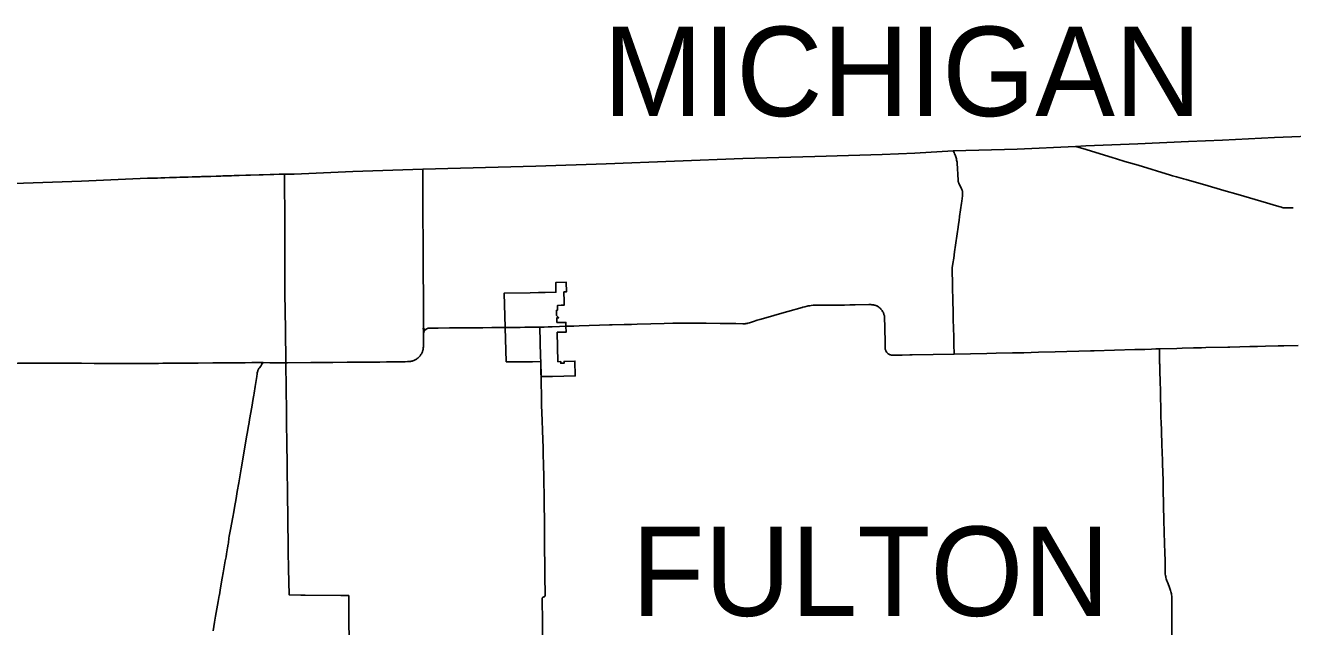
# Model space of a CAD drawing. Extents: x -786946 to -767280, y 417139 to 426807.
# Drawn here: x -783620 to -780299, y 425231 to 426807 of the extents above; entities that cross this region are included whole.
import ezdxf

# ---------------------------------------------------------------- set-up
doc = ezdxf.new("R2010")
doc.units = 0
for name, color, linetype in [('DV_X_Corp_Line', 7, 'Continuous'), ('DV_X_County_Line', 7, 'Continuous'), ('GM_X_State_Route', 7, 'Continuous'), ('SH_Text', 7, 'Continuous')]:
    doc.layers.add(name, color=color, linetype=linetype)

msp = doc.modelspace()

# ---------------------------------------------------------------- linework, layer by layer
at = {"layer": 'DV_X_Corp_Line'}
msp.add_lwpolyline([(-782224.8, 425925.3), (-782217.2, 425925.6), (-782216.9, 425921.4), (-782208, 425921.7), (-782208.2, 425925.9), (-782179.8, 425926.9), (-782178.9, 425888), (-782238.8, 425886.8), (-782268.7, 425886.7), (-782269.6, 425925.5), (-782291.3, 425925.3), (-782304.5, 425925.3), (-782359.9, 425925.1), (-782365.5, 426104.8), (-782297.1, 426106), (-782275.2, 426106.4), (-782257.9, 426106.9), (-782229.5, 426107.5), (-782229.9, 426133.3), (-782202.9, 426134.1), (-782202.1, 426108.3), (-782208.8, 426108.1), (-782207.9, 426082.9), (-782207.7, 426073.9), (-782215.5, 426073.1), (-782225.8, 426072.6), (-782225.6, 426065.9), (-782225.9, 426062.5), (-782225.8, 426060), (-782228, 426060), (-782227.9, 426046.1), (-782222.1, 426040.3), (-782227.4, 426040), (-782226.9, 426028.1), (-782203.5, 426028.3), (-782203.3, 426018), (-782202.9, 426002.7), (-782226, 426002.4)], close=True, dxfattribs=at)
at = {"layer": 'DV_X_County_Line'}
for points in [[(-782771.4, 425130.2), (-782772.4, 425312.1), (-782793.1, 425312.2), (-782887, 425313.2), (-782888.8, 425313.2), (-782892.5, 425313.3), (-782898.3, 425313.5), (-782928.9, 425314.4), (-782930.5, 425382), (-782930.6, 425384.6), (-782930.6, 425387.8), (-782930.7, 425393), (-782930.7, 425400.1), (-782930.9, 425410.7), (-782931, 425422.2), (-782931.1, 425431.4), (-782931.2, 425434.9), (-782931.4, 425443.2), (-782931.4, 425448.7), (-782931.5, 425459.1), (-782931.7, 425471.2), (-782931.8, 425479.5), (-782932, 425493.2), (-782932.1, 425504), (-782932.2, 425511), (-782932.3, 425519), (-782932.4, 425523.2), (-782932.4, 425525.2), (-782932.4, 425527.1), (-782932.6, 425539.8), (-782932.7, 425554.3), (-782932.8, 425561.6), (-782932.8, 425565.5), (-782932.9, 425571.9), (-782933, 425576.8), (-782933, 425580), (-782933.1, 425584.5), (-782933.1, 425589.9), (-782933.2, 425595.2), (-782933.3, 425602.7), (-782933.3, 425608.1), (-782933.5, 425616.1), (-782933.6, 425625.2), (-782933.7, 425632.6), (-782933.7, 425640.1), (-782933.9, 425648.6), (-782934.1, 425665.7), (-782934.2, 425670.7), (-782934.3, 425680.6), (-782934.4, 425687.8), (-782934.6, 425696.7), (-782934.7, 425707.2), (-782935.1, 425726.1), (-782935.2, 425735.4), (-782935.3, 425740.7), (-782935.4, 425741.5), (-782935.4, 425743), (-782935.5, 425752.1), (-782935.6, 425772.3), (-782935.7, 425782.3), (-782935.7, 425787.4), (-782935.8, 425796.7), (-782935.8, 425802.7), (-782936, 425819.7), (-782936.1, 425830.8), (-782936.2, 425838.7), (-782936.3, 425845), (-782936.4, 425851), (-782936.5, 425860.3), (-782936.6, 425870.1), (-782936.8, 425882.8), (-782937, 425893.4), (-782937.1, 425903.6), (-782937.2, 425912.3), (-782937.4, 425922.6), (-782938.6, 426011), (-782939.8, 426104.1), (-782940.2, 426284), (-782941.2, 426417.1), (-782915.4, 426417.3), (-782761.6, 426424.2), (-782578.3, 426430.2), (-782282.2, 426437.5), (-782098, 426444.3), (-781919.2, 426450.6), (-781739.7, 426458.1), (-781551.5, 426463.2), (-781375.1, 426468.8), (-781289.6, 426471.9), (-781188.5, 426477.8), (-781021.2, 426482.7), (-780868.4, 426489.6), (-780840.8, 426490.9), (-780705.2, 426496.6), (-780572.2, 426502.4), (-780483.3, 426506.3), (-780346.7, 426513.1), (-780301.3, 426514.5), (-780212.1, 426518.6)], [(-783650, 426392.7), (-783473.2, 426398.2), (-783300.2, 426406.5), (-783298.5, 426406.3), (-783296.4, 426406.1), (-783293.6, 426406.1), (-783288.5, 426406.1), (-783281.4, 426406.4), (-783273.9, 426406.7), (-783264.9, 426407), (-783254.9, 426407.4), (-783242.3, 426407.8), (-783234.8, 426408), (-783223.9, 426408.4), (-783215.1, 426408.6), (-783208.1, 426408.8), (-783192.9, 426409.3), (-783182.6, 426409.7), (-783171.9, 426410), (-783162.3, 426410.2), (-783158.2, 426410.4), (-783146.1, 426410.7), (-783133.8, 426411.1), (-783119.7, 426411.6), (-783115.4, 426411.7), (-783107.5, 426412), (-783102.5, 426412.2), (-783092.6, 426412.5), (-783087, 426412.6), (-783079.8, 426412.9), (-783073.2, 426413.1), (-783060, 426413.6), (-783042.3, 426414.1), (-783030.9, 426414.5), (-783030.1, 426414.5), (-783007.5, 426415.1), (-782996.4, 426415.5), (-782978.6, 426416), (-782968.9, 426416.3), (-782955, 426416.7), (-782941.2, 426417.1), (-782940.2, 426284), (-782939.8, 426104.1), (-782938.6, 426011), (-782937.4, 425922.6), (-782937.2, 425912.3), (-782937.1, 425903.6), (-782937, 425893.4), (-782936.8, 425882.8), (-782936.6, 425870.1), (-782936.5, 425860.3), (-782936.4, 425851), (-782936.3, 425845), (-782936.2, 425838.7), (-782936.1, 425830.8), (-782936, 425819.7), (-782935.8, 425802.7), (-782935.8, 425796.7), (-782935.7, 425787.4), (-782935.7, 425782.3), (-782935.6, 425772.3), (-782935.5, 425752.1), (-782935.4, 425743), (-782935.4, 425741.5), (-782935.3, 425740.7), (-782935.2, 425735.4), (-782935.1, 425726.1), (-782934.7, 425707.2), (-782934.6, 425696.7), (-782934.4, 425687.8), (-782934.3, 425680.6), (-782934.2, 425670.7), (-782934.1, 425665.7), (-782933.9, 425648.6), (-782933.7, 425640.1), (-782933.7, 425632.6), (-782933.6, 425625.2), (-782933.5, 425616.1), (-782933.3, 425608.1), (-782933.3, 425602.7), (-782933.2, 425595.2), (-782933.1, 425589.9), (-782933.1, 425584.5), (-782933, 425580), (-782933, 425576.8), (-782932.9, 425571.9), (-782932.8, 425565.5), (-782932.8, 425561.6), (-782932.7, 425554.3), (-782932.6, 425539.8), (-782932.4, 425527.1), (-782932.4, 425525.2), (-782932.4, 425523.2), (-782932.3, 425519), (-782932.2, 425511), (-782932.1, 425504), (-782932, 425493.2), (-782931.8, 425479.5), (-782931.7, 425471.2), (-782931.5, 425459.1), (-782931.4, 425448.7), (-782931.4, 425443.2), (-782931.2, 425434.9), (-782931.1, 425431.4), (-782931, 425422.2), (-782930.9, 425410.7), (-782930.7, 425400.1), (-782930.7, 425393), (-782930.6, 425387.8), (-782930.6, 425384.6), (-782930.5, 425382), (-782928.9, 425314.4), (-782898.3, 425313.5), (-782892.5, 425313.3), (-782888.8, 425313.2), (-782887, 425313.2), (-782793.1, 425312.2), (-782772.4, 425312.1), (-782771.4, 425130.2)]]:
    msp.add_lwpolyline(points, dxfattribs=at)
at = {"layer": 'GM_X_State_Route'}
for p, q in [((-781187.4, 425990.5), (-781188.4, 426035.5)), ((-782272, 426015.9), (-782261.7, 426016.1)), ((-782271.8, 426009.5), (-782272, 426015.9)), ((-780712.9, 425956.9), (-780686.2, 425957.7)), ((-780686.2, 425957.7), (-780712.9, 425956.9)), ((-783317.9, 425920.9), (-783308.8, 425920.9)), ((-782260.5, 425565.4), (-782260.7, 425575.3)), ((-783111.6, 425313.2), (-783111.5, 425313.9))]:
    msp.add_line(p, q, dxfattribs=at)
for points in [[(-781177.5, 426431.8), (-781178.4, 426444.6), (-781178.7, 426447.9), (-781179.2, 426451.2), (-781179.7, 426454), (-781180.3, 426456.7), (-781180.9, 426459.4), (-781181.7, 426462.1), (-781182.8, 426465.3), (-781183.8, 426467.9), (-781184.9, 426470.5), (-781186.3, 426473.5), (-781188.5, 426477.9)], [(-780868.4, 426489.7), (-780854.9, 426485.5), (-780840.6, 426481.2), (-780781.2, 426463.1), (-780772.2, 426460.5), (-780760.4, 426456.9), (-780738.5, 426450.4), (-780704.3, 426440.1), (-780618.9, 426414.3), (-780613.6, 426412.8), (-780603.9, 426410.1), (-780585.6, 426405), (-780578.2, 426402.8), (-780569.8, 426400.4), (-780529.4, 426388.6), (-780479.9, 426374.2), (-780442.1, 426363.3), (-780367.3, 426341.3), (-780359.2, 426339), (-780341.5, 426333.8), (-780332, 426330.9), (-780328.8, 426330), (-780326.6, 426329.5), (-780323.9, 426329), (-780321.7, 426328.7), (-780319.4, 426328.5), (-780316.7, 426328.3), (-780312.8, 426328.3), (-780297.7, 426328.6)], [(-782576.9, 426014.3), (-782576.9, 426016.8), (-782577, 426017.4), (-782576.9, 426033), (-782576.9, 426052), (-782576.9, 426070.5), (-782577, 426087.3), (-782577, 426103.3), (-782577, 426106.7), (-782577.2, 426149.9), (-782577.3, 426175.6), (-782577.4, 426190.2), (-782577.7, 426229.9), (-782577.8, 426256.7), (-782577.9, 426265.7), (-782578, 426281.8), (-782578, 426286.6), (-782578.1, 426303.7), (-782578.2, 426323.8), (-782578.3, 426352.3), (-782578.5, 426374.8), (-782578.4, 426411.6), (-782578.3, 426430.3)], [(-781188.4, 426035.5), (-781188.7, 426050.9), (-781189.7, 426090), (-781190.3, 426116.3), (-781190.5, 426125), (-781190.6, 426129.7), (-781191.5, 426165.5), (-781191.5, 426167.7), (-781191.4, 426169.4), (-781191.1, 426171.6), (-781189.4, 426182.6), (-781187.4, 426197), (-781185, 426213.6), (-781182.6, 426230.8), (-781178.4, 426260.1), (-781175.8, 426277.8), (-781174.6, 426286.1), (-781173.4, 426295.6), (-781171.9, 426306), (-781166.7, 426340.9), (-781166, 426346.5), (-781164.6, 426359.8), (-781164.2, 426363.7), (-781164.1, 426365.9), (-781164.2, 426368.2), (-781164.3, 426370.4), (-781164.5, 426372), (-781164.9, 426373.7), (-781165.3, 426375.3), (-781165.9, 426376.8), (-781166.6, 426378.4), (-781168.8, 426382.9), (-781172.8, 426390.9), (-781173.7, 426392.9), (-781174.4, 426394.5), (-781174.9, 426396.1), (-781175.3, 426397.7), (-781175.6, 426399.4), (-781175.7, 426401.1), (-781176.4, 426416.1), (-781177.5, 426431.8)], [(-781758.6, 426025), (-781740.3, 426024.7), (-781736.4, 426024.7), (-781734.1, 426024.8), (-781731.9, 426025.1), (-781731.4, 426025.2), (-781730.3, 426025.3), (-781728.6, 426025.7), (-781726.5, 426026.3), (-781722.2, 426027.6), (-781711.6, 426031), (-781702.5, 426033.8), (-781695.1, 426036), (-781673.6, 426042.1), (-781643.6, 426050.6), (-781621.6, 426056.9), (-781584.2, 426067.5)], [(-781584.2, 426067.5), (-781582.5, 426068), (-781577.1, 426069.4), (-781571.7, 426070.7), (-781568.4, 426071.4), (-781564.6, 426072.1), (-781560.7, 426072.6), (-781555.2, 426073.2), (-781551.9, 426073.5), (-781548, 426073.6), (-781544.8, 426073.7), (-781538, 426073.7), (-781534.6, 426073.6)], [(-781534.6, 426073.6), (-781508.4, 426073.4), (-781499.5, 426073.4), (-781491.7, 426073.5), (-781473.9, 426073.9), (-781459.4, 426074.3), (-781454.3, 426074.4), (-781445.5, 426074.5), (-781409.3, 426074.8), (-781404.3, 426074.8), (-781401.5, 426074.7), (-781400.3, 426074.6), (-781399.3, 426074.5), (-781397.6, 426074.2), (-781396, 426073.9), (-781393.9, 426073.3), (-781391.8, 426072.6), (-781390.9, 426072.3)], [(-781390.9, 426072.3), (-781390.2, 426072), (-781388.7, 426071.3), (-781387.2, 426070.6), (-781385.8, 426069.7), (-781384.4, 426068.8), (-781382.6, 426067.5), (-781380.9, 426066.1), (-781379.2, 426064.6), (-781378.1, 426063.4), (-781377, 426062.2), (-781375.6, 426060.4), (-781374.6, 426059.1), (-781373.5, 426057.2), (-781372.4, 426055.2), (-781371.7, 426053.7), (-781371, 426052.2), (-781370.5, 426050.6), (-781370, 426049), (-781369.6, 426047.4), (-781369.1, 426045.2), (-781368.8, 426043), (-781368.6, 426040.4)], [(-781368.6, 426040.4), (-781368.6, 426040.4), (-781368.5, 426038), (-781368.4, 426033.2), (-781368.2, 426024), (-781367, 425965.1), (-781366.8, 425961.2), (-781366.7, 425959.2)], [(-782578.3, 425955.5), (-782577.9, 425957.1), (-782577.6, 425959.3), (-782577.3, 425961.5), (-782577.1, 425964.3), (-782577, 425967.7), (-782577, 425977.2), (-782576.9, 425984.4), (-782576.5, 425998), (-782576, 426001.4), (-782575.8, 426002.5), (-782575.5, 426003.6), (-782575.1, 426004.7), (-782574.6, 426005.7), (-782574, 426006.7), (-782573, 426008.2), (-782572.5, 426008.7)], [(-782578.3, 425955.5), (-782577.9, 425957.1), (-782577.6, 425959.3), (-782577.3, 425961.5), (-782577.1, 425964.3), (-782577, 425967.7), (-782577, 425977.2), (-782576.9, 425984.4), (-782576.5, 425998), (-782576, 426001.4), (-782575.8, 426002.5), (-782575.5, 426003.6), (-782575.1, 426004.7), (-782574.6, 426005.7), (-782574, 426006.7), (-782573, 426008.2), (-782572.5, 426008.7)], [(-782577.1, 426006.9), (-782577.2, 426013.3), (-782576.9, 426014.3)], [(-782576.5, 425998), (-782576.8, 425999.6), (-782576.9, 426000.8), (-782577, 426002.1), (-782577.1, 426005.1), (-782577.1, 426006.9)], [(-782572.5, 426008.7), (-782574.8, 426010.7), (-782576, 426012), (-782576.5, 426012.8), (-782576.7, 426013.2), (-782576.8, 426013.7), (-782576.9, 426014.3)], [(-782572.5, 426008.7), (-782570.9, 426010), (-782570, 426010.7), (-782568.3, 426011.7), (-782567.4, 426012.1), (-782566.1, 426012.6), (-782565.3, 426012.8), (-782563.2, 426013.1), (-782560.2, 426013.2), (-782557.9, 426013.3)], [(-782557.9, 426013.3), (-782555.7, 426013.4), (-782537.9, 426013.6), (-782508.3, 426013.9), (-782420.8, 426014.4), (-782397.9, 426014.6), (-782391.8, 426014.6), (-782373.4, 426014.8), (-782365.6, 426014.9), (-782362.8, 426015)], [(-782362.8, 426015), (-782362.7, 426015), (-782336.1, 426015.2)], [(-782336.1, 426015.2), (-782334.8, 426015.2), (-782330, 426015.1), (-782323.8, 426015.3), (-782311, 426015.4), (-782305, 426015.5), (-782294.3, 426015.7)], [(-782294.3, 426015.7), (-782293.7, 426015.7), (-782283.3, 426015.8)], [(-782283.3, 426015.8), (-782283, 426015.8), (-782272, 426015.9)], [(-782271.4, 425998.5), (-782271.5, 425999.6), (-782271.6, 426004.6), (-782271.8, 426009.5)], [(-782269.6, 425925.5), (-782269.6, 425928.1), (-782269.8, 425935.4), (-782270, 425939.9), (-782270.2, 425948.8), (-782270.3, 425950.5), (-782270.4, 425953.3), (-782270.6, 425962.8), (-782270.6, 425964.5), (-782270.7, 425967.8), (-782270.8, 425972.3), (-782271, 425980.1), (-782271.2, 425988.4), (-782271.3, 425993.8), (-782271.4, 425998.5)], [(-782261.7, 426016.1), (-782260.8, 426016.1), (-782250.2, 426016.6), (-782244.3, 426016.8), (-782239.5, 426016.9), (-782220.5, 426017.5), (-782203.3, 426018), (-782203.3, 426018)], [(-782203.3, 426018), (-782198.1, 426018.2), (-782187.5, 426018.6), (-782182.8, 426018.7)], [(-782182.8, 426018.7), (-782168.6, 426019.2), (-782088.9, 426021.8), (-782082.4, 426021.9)], [(-782082.4, 426021.9), (-782050.5, 426022.7), (-782031.6, 426023.2), (-782016.5, 426023.5), (-781980.9, 426024.4), (-781946.4, 426025.5), (-781923, 426026.1), (-781910, 426026.3), (-781906.8, 426026.4), (-781885.7, 426026.2), (-781864.5, 426026), (-781855, 426026), (-781836.1, 426025.9), (-781799.3, 426025.5), (-781758.6, 426025)], [(-781186.4, 425945.2), (-781186.5, 425950.8), (-781186.7, 425964.8), (-781187, 425977.1), (-781187.3, 425986), (-781187.4, 425990.5)], [(-780648.4, 425958.8), (-780602.8, 425960.1), (-780588.3, 425960.6), (-780558.9, 425961.4), (-780541.5, 425961.9), (-780537.7, 425962)], [(-780537.7, 425962), (-780526.5, 425962.2), (-780469.2, 425963.6), (-780463.5, 425963.8), (-780411.7, 425965), (-780391.7, 425965.3), (-780370.5, 425965.7), (-780337.1, 425966.7), (-780330.9, 425966.9), (-780322.6, 425967.1), (-780284.8, 425967.6)], [(-782611.3, 425926), (-782610.9, 425926), (-782608.7, 425926.4), (-782606.6, 425926.9), (-782604.4, 425927.5), (-782602.3, 425928.2), (-782600.3, 425929.1), (-782598.7, 425929.8), (-782596.8, 425930.8), (-782594.9, 425932), (-782593.1, 425933.3), (-782591.3, 425934.6), (-782589.7, 425936.1), (-782588.1, 425937.7), (-782587, 425938.9), (-782585.5, 425940.6), (-782584.2, 425942.4), (-782583.3, 425943.8), (-782582.2, 425945.7), (-782581, 425947.9), (-782580.2, 425949.7), (-782579.6, 425951.2), (-782579, 425952.8), (-782578.4, 425954.9), (-782578.3, 425955.5)], [(-782611.3, 425926), (-782610.9, 425926), (-782608.7, 425926.4), (-782606.6, 425926.9), (-782604.4, 425927.5), (-782602.3, 425928.2), (-782600.3, 425929.1), (-782598.7, 425929.8), (-782596.8, 425930.8), (-782594.9, 425932), (-782593.1, 425933.3), (-782591.3, 425934.6), (-782589.7, 425936.1), (-782588.1, 425937.7), (-782587, 425938.9), (-782585.5, 425940.6), (-782584.2, 425942.4), (-782583.3, 425943.8), (-782582.2, 425945.7), (-782581, 425947.9), (-782580.2, 425949.7), (-782579.6, 425951.2), (-782579, 425952.8), (-782578.4, 425954.9), (-782578.3, 425955.5)], [(-781366.7, 425959.2), (-781366.5, 425958), (-781366.1, 425956.4), (-781365.6, 425954.8), (-781364.9, 425953.3)], [(-781364.9, 425953.3), (-781364.1, 425951.8), (-781363.1, 425950.4), (-781362.1, 425949.1), (-781361.3, 425948.2), (-781360.1, 425947.1), (-781358.7, 425946), (-781357.3, 425945.1), (-781355.9, 425944.3), (-781354.3, 425943.6), (-781352.9, 425943.1), (-781350.5, 425942.4), (-781349.4, 425942.3), (-781346.1, 425942.2), (-781337.2, 425942.4), (-781322.1, 425942.7), (-781302.6, 425943.1), (-781295.9, 425943.2), (-781186.4, 425945.2)], [(-781186.4, 425945.2), (-781100.5, 425946.9), (-781076.5, 425947.4), (-781033.1, 425948.3), (-781003.6, 425948.9), (-780965.1, 425949.9), (-780921.7, 425951), (-780828.6, 425953.4), (-780819.3, 425953.6), (-780712.9, 425956.9)], [(-780712.9, 425956.9), (-780819.3, 425953.6), (-780828.6, 425953.4), (-780921.7, 425951), (-780965.1, 425949.9), (-781003.6, 425948.9), (-781033.1, 425948.3), (-781076.5, 425947.4), (-781100.5, 425946.9), (-781186.4, 425945.2)], [(-780686.2, 425957.7), (-780669.2, 425958.3), (-780657.5, 425958.6), (-780648.4, 425958.8)], [(-780648.4, 425958.8), (-780657.5, 425958.6), (-780669.2, 425958.3), (-780686.2, 425957.7)], [(-780638.7, 425597.3), (-780638.9, 425618.7), (-780639.1, 425630.4), (-780640, 425662.8), (-780640.4, 425671.8), (-780640.7, 425682.4), (-780641.8, 425713.1), (-780642.1, 425720.4), (-780642.5, 425730.4), (-780643, 425744.4), (-780643.9, 425767.8), (-780644.2, 425778.1), (-780645, 425808.6), (-780645.4, 425828.2), (-780645.8, 425841), (-780646.7, 425881.3), (-780647, 425892.4), (-780647.6, 425918.1), (-780647.7, 425920.4), (-780647.7, 425924.3), (-780647.7, 425926.8), (-780648, 425940.4), (-780648.3, 425951.5), (-780648.4, 425958.8)], [(-783650.5, 425920.3), (-783643.5, 425920.9), (-783639.5, 425921.2), (-783635.1, 425921.3), (-783579.5, 425921.3), (-783565.8, 425921.2), (-783532.4, 425921.2), (-783524.3, 425921.2), (-783495.7, 425921.2), (-783473.2, 425921.1), (-783439.9, 425921), (-783414.6, 425920.9), (-783397.2, 425920.9), (-783379.7, 425920.8), (-783355.1, 425920.9), (-783332.6, 425920.9), (-783321.7, 425921)], [(-783321.7, 425921), (-783321.5, 425921), (-783317.9, 425920.9)], [(-783308.8, 425920.9), (-783305.7, 425920.9), (-783294.1, 425920.9), (-783282.6, 425920.9), (-783270.9, 425921), (-783260.1, 425921.1)], [(-783260.1, 425921.1), (-783248.6, 425921.1), (-783236.6, 425921.2), (-783225.3, 425921.3), (-783213.8, 425921.3), (-783205.2, 425921.4), (-783202.5, 425921.4)], [(-783202.5, 425921.4), (-783196.9, 425921.5), (-783177.4, 425921.6), (-783166.7, 425921.6)], [(-783166.7, 425921.6), (-783128.7, 425921.9), (-783104.5, 425922.1), (-783043.9, 425922.7), (-783026.4, 425922.8), (-783012.6, 425922.8), (-783002.1, 425922.8), (-782997, 425922.8)], [(-783111.5, 425313.9), (-783108.2, 425332.8), (-783103.8, 425357.7), (-783101.4, 425371.7), (-783096, 425402.9), (-783094.1, 425413.4), (-783092.7, 425421.8), (-783089.9, 425437), (-783088.2, 425447.4), (-783087.7, 425450.8), (-783087.5, 425452.9), (-783086.8, 425460.2), (-783086.5, 425462.9), (-783085.6, 425468), (-783084, 425477.1), (-783082.5, 425485), (-783076.5, 425517.7), (-783074, 425532), (-783071.1, 425548.7), (-783068.8, 425561.3), (-783066.8, 425573), (-783064.5, 425585.4), (-783060.6, 425608), (-783054.1, 425644.6), (-783050.8, 425664.4), (-783044.6, 425702.3), (-783041.2, 425722.5), (-783040.3, 425728.2), (-783038, 425741.7), (-783036.1, 425752.7), (-783034.6, 425761.3), (-783033.8, 425766.1), (-783032.5, 425773.6), (-783026.9, 425806.1), (-783022.9, 425829.1), (-783021.4, 425837.7), (-783020.6, 425843.2), (-783017.7, 425860.1), (-783013.7, 425886.2), (-783012.6, 425893.2), (-783012.1, 425896.1), (-783011.6, 425898.4), (-783011.1, 425900.2), (-783010.5, 425902), (-783009.7, 425903.8), (-783008.8, 425905.6), (-783007.8, 425907.3), (-783006.6, 425909.2), (-783003.2, 425913.7), (-783000, 425918.5), (-782997, 425922.8)], [(-783000, 425918.5), (-783000, 425919.1), (-783000.2, 425920), (-783000.4, 425920.7), (-783000.7, 425921.2), (-783001.1, 425921.7), (-783001.6, 425922.3), (-783002.1, 425922.8)], [(-782997, 425922.8), (-782979.7, 425922.7), (-782937.5, 425922.7)], [(-782997, 425922.8), (-782979.7, 425922.7), (-782937.5, 425922.7)], [(-782937.5, 425922.7), (-782932.8, 425922.7), (-782871.5, 425923.3), (-782855.9, 425923.4), (-782849.8, 425923.5), (-782838.6, 425923.5), (-782822.5, 425923.6), (-782814.1, 425923.5), (-782776.8, 425923.7), (-782759, 425923.8), (-782754, 425923.8), (-782745.1, 425923.9), (-782737.8, 425923.9), (-782728.9, 425924.1), (-782691, 425924.5), (-782673.2, 425924.7), (-782644.8, 425925.1), (-782624.8, 425925.3), (-782618.7, 425925.4), (-782615.3, 425925.6), (-782613.1, 425925.8), (-782611.3, 425926)], [(-782937.5, 425922.7), (-782932.8, 425922.7), (-782871.5, 425923.3), (-782855.9, 425923.4), (-782849.8, 425923.5), (-782838.6, 425923.5), (-782822.5, 425923.6), (-782814.1, 425923.5), (-782776.8, 425923.7), (-782759, 425923.8), (-782754, 425923.8), (-782745.1, 425923.9), (-782737.8, 425923.9), (-782728.9, 425924.1), (-782691, 425924.5), (-782673.2, 425924.7), (-782644.8, 425925.1), (-782624.8, 425925.3), (-782618.7, 425925.4), (-782615.3, 425925.6), (-782613.1, 425925.8), (-782611.3, 425926)], [(-782268.7, 425886.7), (-782268.9, 425893.7), (-782269.2, 425908.2), (-782269.6, 425925.5)], [(-782261.5, 425615), (-782261.6, 425622.2), (-782262.2, 425656.8), (-782262.8, 425680.9), (-782263, 425686.5), (-782263.5, 425698.2), (-782265.1, 425745), (-782266, 425771.3), (-782266.6, 425790.9), (-782267.1, 425811.6), (-782267.2, 425818.8), (-782267.6, 425841.7), (-782268.1, 425864.7), (-782268.5, 425877.3), (-782268.7, 425886.7)], [(-782260.7, 425575.3), (-782261.4, 425610.5), (-782261.5, 425615)], [(-780633.2, 425376.2), (-780633.4, 425381.9), (-780633.6, 425396.4), (-780634.5, 425432.1), (-780634.6, 425440.5), (-780635.8, 425486.1), (-780636.3, 425501.9), (-780636.5, 425512), (-780637.4, 425545.5), (-780637.6, 425555), (-780638.4, 425586.3), (-780638.6, 425594.1), (-780638.7, 425597.3)], [(-782265.2, 425193.2), (-782265.2, 425242.9), (-782265.5, 425303.8), (-782265.4, 425304.9), (-782265.3, 425305.4), (-782265.2, 425306), (-782265, 425306.5), (-782264.8, 425306.9), (-782264.5, 425307.3), (-782264.1, 425307.7), (-782263.7, 425308), (-782263.2, 425308.2), (-782262.7, 425308.4), (-782261, 425308.8), (-782260.5, 425308.9), (-782259.9, 425309.1), (-782259.5, 425309.5), (-782259, 425309.8), (-782258.7, 425310.3), (-782258.4, 425310.8), (-782258.3, 425311.4), (-782258.1, 425311.9), (-782258, 425312.5), (-782258, 425313.6), (-782258.2, 425327.1), (-782258.6, 425351), (-782258.9, 425376.2), (-782259, 425384.8), (-782259.1, 425390.2), (-782259.1, 425397.5), (-782259.4, 425431), (-782259.7, 425453.9), (-782260, 425486.9), (-782260, 425510.3), (-782260.4, 425548.9), (-782260.5, 425565.4)], [(-780615.9, 425159.4), (-780615.8, 425236), (-780615.7, 425247.1), (-780615.7, 425296.8), (-780615.8, 425304.7), (-780615.9, 425307.5), (-780616.1, 425310.8), (-780616.5, 425314.2), (-780616.9, 425316.9), (-780617.3, 425319.1), (-780617.5, 425320.1), (-780618, 425322.4), (-780618.9, 425325.6), (-780619.8, 425328.3), (-780620.7, 425330.9), (-780622.6, 425335.6), (-780627.5, 425347.5), (-780628.9, 425351.1), (-780629.8, 425353.8), (-780630.5, 425356.4), (-780631.3, 425359.7), (-780631.9, 425362.4), (-780632.3, 425364.9), (-780632.8, 425368.5), (-780633, 425371.8), (-780633.2, 425374.6), (-780633.2, 425376.2)], [(-783128.1, 425219.4), (-783124.2, 425242.3), (-783122.4, 425252.6), (-783121.3, 425258.6), (-783119.6, 425268.2), (-783114.6, 425296.3), (-783111.8, 425312.1), (-783111.6, 425313.2)]]:
    msp.add_lwpolyline(points, dxfattribs=at)

# ---------------------------------------------------------------- texts
at = {"layer": 'SH_Text'}
for s, p in [('MICHIGAN', (-782105.5, 426569.1)), ('FULTON', (-782032, 425258.9))]:
    msp.add_text(s, height=234.38, dxfattribs=at).set_placement(p)

doc.saveas('drawing.dxf')
